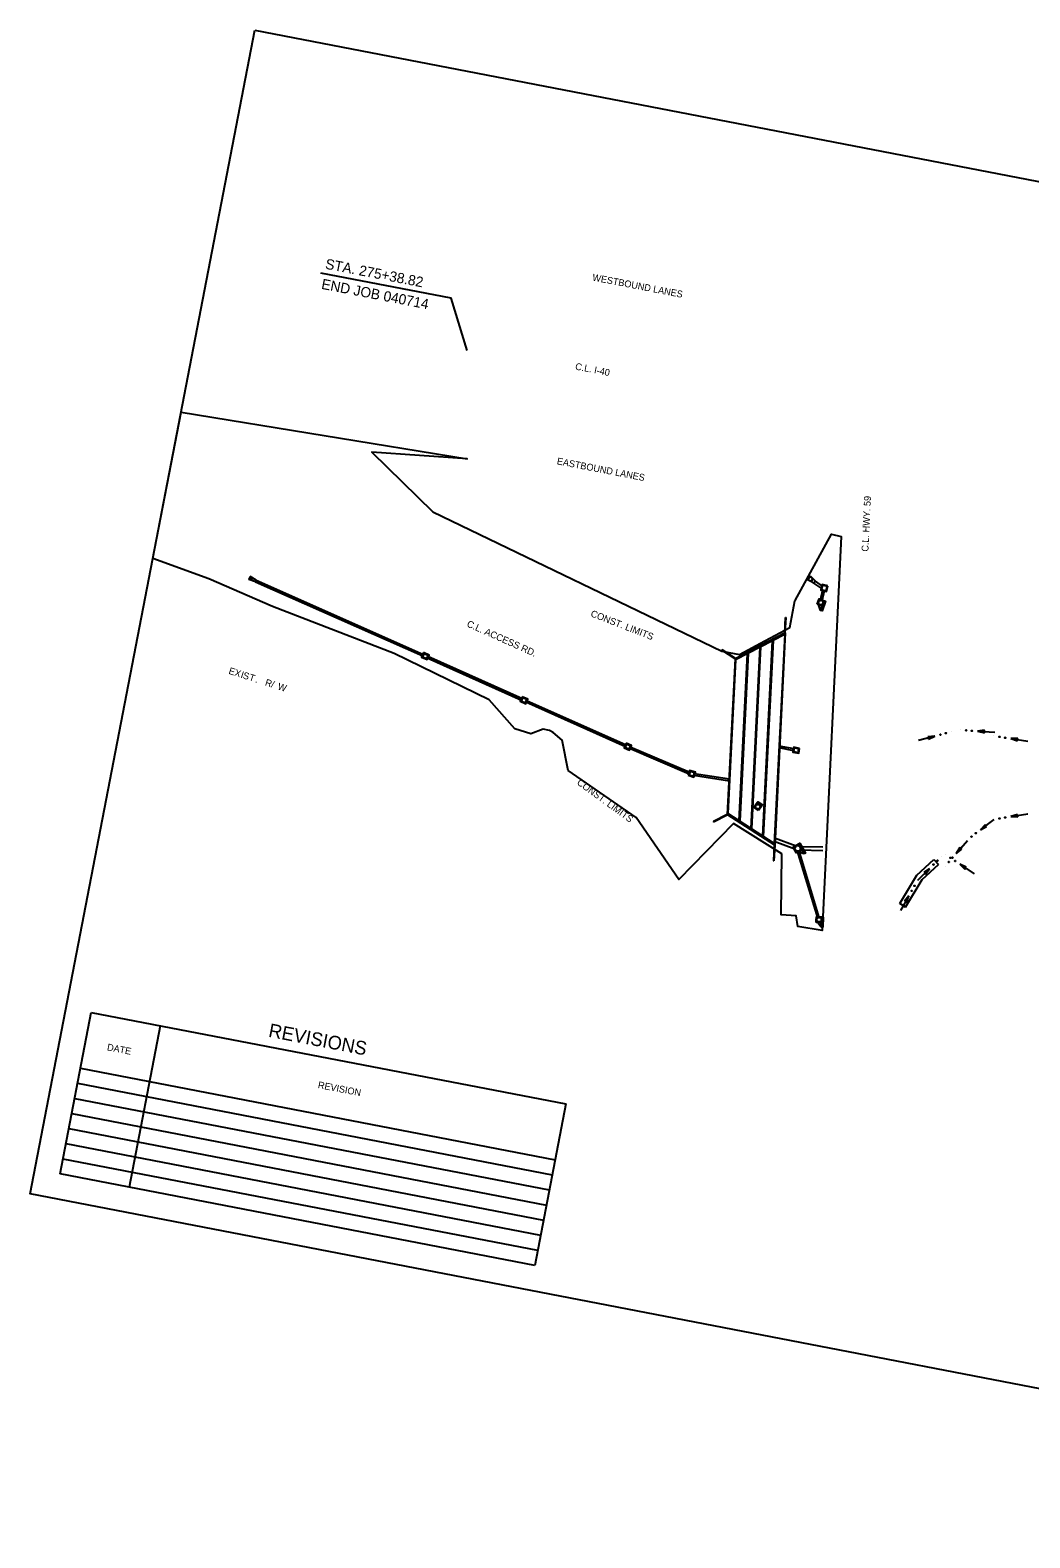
# Model space of a CAD drawing. Extents: x 607205 to 611729, y 416008 to 419873.
# Drawn here: x 609974 to 610853, y 418547 to 419873 of the extents above; entities that cross this region are included whole.
import ezdxf

# ---------------------------------------------------------------- set-up
doc = ezdxf.new("R2010")
doc.units = 0
for name, color, linetype in [('Default', 7, 'Continuous'), ('Level 43', 7, 'Continuous'), ('R_Concrete', 7, 'Continuous'), ('R_Draft', 7, 'Continuous'), ('R_Drainage', 7, 'Continuous'), ('TP_Mask', 7, 'Continuous'), ('X_ARROWS_LEGEND', 7, 'Continuous')]:
    doc.layers.add(name, color=color, linetype=linetype)

msp = doc.modelspace()

# ---------------------------------------------------------------- linework, layer by layer
at = {"layer": 'Level 43'}
for p, q in [((610792.4, 419257.9), (610792.4, 419257.9)), ((610769.8, 419252.5), (610755.3, 419248.6)), ((610769.8, 419252.5), (610763.7, 419251.9)), ((610763.7, 419251.9), (610764.3, 419249.9)), ((610764.3, 419249.9), (610769.8, 419252.5)), ((610784.3, 419256.3), (610784.3, 419256.3)), ((610813.5, 419257.6), (610807.4, 419256.9)), ((610807.4, 419256.9), (610822.4, 419255.9)), ((610807.4, 419256.9), (610813.3, 419255.5)), ((610813.3, 419255.5), (610813.5, 419257.6)), ((610821.7, 419252.7), (610821.7, 419252.7)), ((610842.7, 419250.5), (610836.6, 419250.4)), ((610836.6, 419250.4), (610851.4, 419248.1)), ((610836.6, 419250.4), (610842.3, 419248.4)), ((610842.3, 419248.4), (610842.7, 419250.5)), ((610850.6, 419248), (610850.5, 419248)), ((610809.9, 419170.1), (610821.9, 419179.2)), ((610821.7, 419179.3), (610821.7, 419179.3)), ((610836.5, 419181.7), (610851.4, 419184.1)), ((610842.3, 419183.7), (610836.5, 419181.7)), ((610836.5, 419181.7), (610842.6, 419181.6)), ((610842.6, 419181.6), (610842.3, 419183.7)), ((610851.4, 419183.8), (610851.3, 419183.8)), ((610814, 419174.6), (610809.9, 419170.1)), ((610809.9, 419170.1), (610815.3, 419172.9)), ((610815.3, 419172.9), (610814, 419174.6)), ((610788.6, 419149.4), (610798.5, 419160.7)), ((610791.8, 419154.6), (610788.6, 419149.4)), ((610788.6, 419149.4), (610793.4, 419153.2)), ((610793.4, 419153.2), (610791.8, 419154.6)), ((610797.9, 419161.1), (610797.8, 419161.1)), ((610775.8, 419146.5), (610775.8, 419146.5)), ((610779.5, 419148.4), (610779.4, 419148.4)), ((610791.8, 419139.9), (610804.2, 419131.4)), ((610791.8, 419139.9), (610796.1, 419135.6)), ((610797.4, 419137.3), (610791.8, 419139.9)), ((610754.4, 419125.1), (610754.4, 419125.1)), ((610765.1, 419135.9), (610754.5, 419125.4)), ((610765.1, 419135.9), (610760.1, 419132.5)), ((610760.1, 419132.5), (610761.6, 419131)), ((610761.6, 419131), (610765.1, 419135.9)), ((610778.8, 419138), (610778.8, 419138)), ((610796.1, 419135.6), (610797.4, 419137.3)), ((610746.9, 419112.1), (610739.5, 419099.1)), ((610746.9, 419112.1), (610743, 419107.4)), ((610744.8, 419106.3), (610746.9, 419112.1)), ((610743, 419107.4), (610744.8, 419106.3))]:
    msp.add_line(p, q, dxfattribs=at)
for centre in [(610797.4, 419257.6), (610774.6, 419253.8), (610779.5, 419255.1), (610802.4, 419257.2), (610826.7, 419251.9), (610831.6, 419251.1), (610826.7, 419180.1), (610831.6, 419180.9), (610805.9, 419167.1), (610801.9, 419164.1), (610768.7, 419139.5), (610772.2, 419143), (610782.1, 419141.8), (610783.6, 419145.5), (610785.4, 419145.6), (610787.7, 419142.7), (610749.4, 419116.4), (610751.8, 419120.8)]:
    msp.add_circle(centre, 0.375, dxfattribs=at)
at = {"layer": 'R_Concrete'}
for p, q in [((610768.9, 419144.1), (610773, 419139.7)), ((610744.1, 419102.1), (610739, 419105.2))]:
    msp.add_line(p, q, dxfattribs=at)
for points in [[(610739, 419105.2), (610753.9, 419130.2), (610768.9, 419144.1)], [(610744.1, 419102.1), (610758.6, 419126.4), (610773, 419139.7)]]:
    msp.add_lwpolyline(points, dxfattribs=at)
at = {"layer": 'R_Draft'}
msp.add_lwpolyline([(610358.7, 419591.5), (610344.5, 419637.5), (610230, 419659.6)], dxfattribs=at)
at = {"layer": 'R_Drainage'}
for p, q in [((610167.8, 419392.8), (610166.5, 419390.1)), ((610173, 419389.6), (610167.8, 419392.8)), ((610169, 419391.6), (610167.8, 419392.8)), ((610660.3, 419393.1), (610658, 419389.9)), ((610664.7, 419388.8), (610660.3, 419393.1)), ((610660.3, 419393.1), (610662.1, 419390.8)), ((610172.4, 419388.3), (610166.5, 419390.1)), ((610168.2, 419389.9), (610166.5, 419390.1)), ((610173, 419389.6), (610172.4, 419388.3)), ((610172.4, 419388.3), (610319.7, 419323)), ((610173, 419389.6), (610320.3, 419324.3)), ((610663.5, 419387.1), (610658, 419389.9)), ((610658, 419389.9), (610660.8, 419389)), ((610664.7, 419388.8), (610663.5, 419387.1)), ((610670.4, 419382.2), (610663.5, 419387.1)), ((610670.9, 419384.3), (610664.7, 419388.8)), ((610669.3, 419371.9), (610671.4, 419381)), ((610670.8, 419371.6), (610672.8, 419380.6)), ((610666.4, 419368.4), (610668.1, 419373.1)), ((610669.3, 419363.1), (610667.2, 419369.1)), ((610669.7, 419363), (610672.8, 419371.4)), ((610637.8, 419342.9), (610638.5, 419356.9)), ((610638.3, 419343.2), (610639, 419356.9)), ((610638.5, 419356.9), (610639, 419356.9)), ((610638.5, 419356.9), (610639, 419356.9)), ((610638.5, 419356.9), (610639, 419356.9)), ((610638.3, 419343.2), (610594.1, 419320.6)), ((610637.8, 419341.8), (610594.6, 419319.7)), ((610637.8, 419341.8), (610628.5, 419158.1)), ((610638.3, 419343.2), (610629, 419156.6)), ((610582.6, 419328), (610582.9, 419328.4)), ((610582.6, 419328), (610582.9, 419328.4)), ((610582.6, 419328), (610582.9, 419328.4)), ((610594.1, 419320.6), (610582.6, 419328)), ((610594.6, 419320.8), (610582.9, 419328.4)), ((610604.9, 419324.9), (610597.5, 419178.1)), ((610605.6, 419325.3), (610598.2, 419177.7)), ((610615.8, 419330.6), (610607.9, 419171.4)), ((610616.5, 419330.9), (610608.5, 419171)), ((610626.8, 419336.2), (610618.2, 419164.8)), ((610627.5, 419336.5), (610618.8, 419164.3)), ((610323.4, 419321.4), (610406.4, 419284.2)), ((610324, 419322.7), (610407.1, 419285.6)), ((610594.1, 419320.6), (610587.3, 419183.6)), ((610594.6, 419319.7), (610587.8, 419184.4)), ((610410.1, 419282.6), (610497.7, 419243.4)), ((610410.7, 419283.9), (610498.3, 419244.7)), ((610501.4, 419241.8), (610553.9, 419219.2)), ((610502, 419243.1), (610554.3, 419220.7)), ((610646.1, 419241.2), (610632.8, 419243.8)), ((610645.8, 419239.7), (610632.8, 419242.3)), ((610557.7, 419218.1), (610589.3, 419213.3)), ((610558.2, 419219.5), (610589.3, 419214.8)), ((610587.3, 419183.6), (610575.1, 419177.3)), ((610587.8, 419183.2), (610575.3, 419176.9)), ((610629, 419156.6), (610587.3, 419183.6)), ((610628.5, 419158.1), (610587.8, 419184.4)), ((610614.8, 419187.1), (610610.7, 419189.9)), ((610575.1, 419177.3), (610575.3, 419176.9)), ((610628.5, 419156.9), (610627.8, 419142.9)), ((610629, 419156.6), (610628.3, 419142.9)), ((610646.8, 419153), (610628.6, 419159.8)), ((610647.8, 419155.8), (610628.8, 419162.9)), ((610655.3, 419149.1), (610650.3, 419157.8)), ((610668.2, 419093.1), (610650.6, 419151.6)), ((610671.2, 419151.7), (610651.1, 419152.2)), ((610671.3, 419154.7), (610651.2, 419155.2)), ((610627.8, 419142.9), (610628.3, 419142.9)), ((610654.8, 419148.9), (610648.3, 419150.8)), ((610666.8, 419092.6), (610649.1, 419151.2)), ((610665.4, 419088.7), (610665.7, 419093.7)), ((610669.7, 419084.5), (610666, 419089.6)), ((610670.2, 419084.5), (610670.7, 419093.5))]:
    msp.add_line(p, q, dxfattribs=at)
for points in [[(610675.6, 419384.6), (610670.8, 419385.8), (610669.6, 419380.9), (610674.4, 419379.7)], [(610675, 419384.2), (610671.1, 419385.2), (610670.2, 419381.3), (610674.1, 419380.3)], [(610666.4, 419368.4), (610668.1, 419373.1), (610672.8, 419371.4), (610671.1, 419366.7)], [(610669.3, 419363.1), (610672.3, 419371.6), (610673.7, 419371.1), (610670.7, 419362.6)], [(610320.3, 419325.9), (610318.5, 419322), (610323.4, 419319.8), (610325.2, 419323.7)], [(610320.6, 419325), (610319.4, 419322.3), (610323.1, 419320.7), (610324.3, 419323.4)], [(610407, 419287.1), (610405.3, 419283.2), (610410.1, 419281), (610411.9, 419284.9)], [(610407.4, 419286.2), (610406.1, 419283.5), (610409.8, 419281.9), (610411, 419284.6)], [(610498.3, 419246.3), (610496.5, 419242.3), (610501.4, 419240.2), (610503.2, 419244.1)], [(610498.6, 419245.4), (610497.4, 419242.7), (610501.1, 419241), (610502.3, 419243.8)], [(610650.9, 419241.7), (610645.7, 419242.7), (610644.9, 419238.5), (610650.1, 419237.4)], [(610650.1, 419241.2), (610646.2, 419241.9), (610645.6, 419239), (610649.6, 419238.2)], [(610552.8, 419218.1), (610557.9, 419216.5), (610559.2, 419220.7), (610554.1, 419222.2)], [(610553.7, 419218.5), (610557.5, 419217.4), (610558.4, 419220.2), (610554.5, 419221.4)], [(610614.8, 419187.1), (610610.7, 419189.9), (610613.5, 419194), (610617.6, 419191.2)], [(610617.4, 419190.8), (610613.2, 419193.6), (610614.1, 419194.8), (610618.2, 419192)], [(610648.1, 419149.6), (610645.1, 419154.8), (610650.3, 419157.8), (610653.3, 419152.6)], [(610654.8, 419148.9), (610649.8, 419157.6), (610651.1, 419158.3), (610656.1, 419149.6)], [(610665.4, 419088.7), (610665.7, 419093.7), (610670.7, 419093.5), (610670.4, 419088.5)], [(610669.7, 419084.5), (610670.2, 419093.5), (610671.7, 419093.4), (610671.2, 419084.4)]]:
    msp.add_lwpolyline(points, close=True, dxfattribs=at)
for centre, radius in [((610669.6, 419369.9), 2.5), ((610669.6, 419369.9), 2.5), ((610669.6, 419369.9), 2), ((610669.6, 419369.9), 2), ((610614.2, 419190.5), 2.5), ((610614.2, 419190.5), 2.5), ((610614.2, 419190.5), 2), ((610614.2, 419190.5), 2), ((610649.2, 419153.7), 3), ((610649.2, 419153.7), 3), ((610649.2, 419153.7), 2.5), ((610649.2, 419153.7), 2.5), ((610668, 419091.1), 2.5), ((610668, 419091.1), 2.5), ((610668, 419091.1), 2), ((610668, 419091.1), 2)]:
    msp.add_circle(centre, radius, dxfattribs=at)
for centre, radius, start, end in [((610168.3, 419390.9), 1, 265.2018, 46.4877), ((610661.1, 419390.1), 1.17, 251.887, 36.8271)]:
    msp.add_arc(centre, radius, start, end, dxfattribs=at)
at = {"layer": 'TP_Mask'}
for points in [[(610171.9, 419873.3), (611428.7, 419630.7), (611419.3, 419582), (611533.5, 419560), (611729, 419522.3), (611726, 419507.1), (611540.8, 418547.5), (609974.4, 418849.9)], [(610082.2, 419408.8), (610107.1, 419537.4), (610358.7, 419496.2), (610274.7, 419502.2), (610328.4, 419449.7), (610582.6, 419327.2), (610597.9, 419324.4), (610620.2, 419336.2), (610642.4, 419348), (610646.8, 419371.4), (610647, 419371.7), (610678.8, 419430.1), (610687.3, 419427.9), (610670.8, 419081.5), (610649.3, 419085.1), (610647.8, 419094.6), (610634.7, 419095.4), (610635.3, 419148.9), (610592.6, 419175.7), (610544.7, 419126.5), (610507.1, 419180.8), (610447.4, 419222.2), (610442, 419249), (610434.1, 419255.7), (610430.9, 419257.5), (610425.5, 419258.5), (610414.5, 419254.5), (610400.6, 419258.8), (610378, 419284.3), (610294.4, 419325.2), (610187.4, 419366.6), (610131.5, 419390.8)], [(610082.2, 419408.8), (610107.1, 419537.4), (610358.7, 419496.2), (610274.7, 419502.2), (610328.4, 419449.7), (610582.6, 419327.2), (610597.9, 419324.4), (610620.2, 419336.2), (610642.4, 419348), (610646.8, 419371.4), (610647, 419371.7), (610678.8, 419430.1), (610687.3, 419427.9), (610670.8, 419081.5), (610649.3, 419085.1), (610647.8, 419094.6), (610634.7, 419095.4), (610635.3, 419148.9), (610592.6, 419175.7), (610544.7, 419126.5), (610507.1, 419180.8), (610447.4, 419222.2), (610442, 419249), (610434.1, 419255.7), (610430.9, 419257.5), (610425.5, 419258.5), (610414.5, 419254.5), (610400.6, 419258.8), (610378, 419284.3), (610294.4, 419325.2), (610187.4, 419366.6), (610131.5, 419390.8)]]:
    msp.add_lwpolyline(points, close=True, dxfattribs=at)
at = {"layer": 'X_ARROWS_LEGEND'}
for p, q in [((610000.7, 418867.6), (610028, 419009.5)), ((610028, 419009.5), (610445.3, 418929)), ((610088.7, 418997.8), (610061.3, 418855.9)), ((610018.6, 418960.4), (610435.9, 418879.9)), ((610016, 418947.2), (610433.3, 418866.6)), ((610013.5, 418933.9), (610430.7, 418853.4)), ((610445.3, 418929), (610418, 418787.1)), ((610010.9, 418920.7), (610428.2, 418840.1)), ((610010.9, 418920.7), (610428.2, 418840.1)), ((610008.3, 418907.4), (610425.6, 418826.9)), ((610005.8, 418894.2), (610423.1, 418813.6)), ((610003.2, 418880.9), (610420.5, 418800.4)), ((610418, 418787.1), (610000.7, 418867.6))]:
    msp.add_line(p, q, dxfattribs=at)

# ---------------------------------------------------------------- texts
at = {"layer": 'Default'}
for s, rotation, p in [('C.L. HWY. 59', 87.2385, (610711.3, 419414.6)), ('C.L. ACCESS RD.', 335.8864, (610357.7, 419349.1))]:
    msp.add_text(s, height=6, rotation=rotation, dxfattribs=at).set_placement(p)
at = {"layer": 'R_Draft'}
for s, height, rotation, p in [('STA. 275+38.82', 9, 349.0919, (610233.3, 419663.6)), ('WESTBOUND LANES', 6, 349.0745, (610468.3, 419653.2)), ('END JOB 040714', 9, 349.0745, (610229.9, 419645.9)), ('C.L. I-40', 6, 349.0745, (610453.2, 419574.9)), ('EASTBOUND LANES', 6, 349.0745, (610437.1, 419491.6)), ('CONST. LIMITS', 6, 338.6841, (610466.6, 419358)), ('E', 6, 342.3857, (610148.4, 419307.4)), ('X', 6, 342.3857, (610153.5, 419305.8)), ('I', 6, 342.3857, (610159, 419304)), ('S', 6, 342.3857, (610160.9, 419303.4)), ('T', 6, 342.3857, (610166.3, 419301.7)), ('.', 6, 342.3857, (610171.9, 419299.9)), ('R', 6, 342.3857, (610180.4, 419297.2)), ('/', 6, 342.3857, (610185.8, 419295.5)), ('W', 6, 342.3857, (610191.4, 419293.7)), ('CONST. LIMITS', 6, 323.9795, (610454.5, 419210.5))]:
    msp.add_text(s, height=height, rotation=rotation, dxfattribs=at).set_placement(p)
at = {"layer": 'X_ARROWS_LEGEND'}
for s, height, p in [('REVISIONS', 12, (610183.3, 418988.2)), ('DATE', 6, (610041.6, 418976.3)), ('REVISION', 6, (610227, 418943.1))]:
    msp.add_text(s, height=height, rotation=349.0745, dxfattribs=at).set_placement(p)

doc.saveas('drawing.dxf')
